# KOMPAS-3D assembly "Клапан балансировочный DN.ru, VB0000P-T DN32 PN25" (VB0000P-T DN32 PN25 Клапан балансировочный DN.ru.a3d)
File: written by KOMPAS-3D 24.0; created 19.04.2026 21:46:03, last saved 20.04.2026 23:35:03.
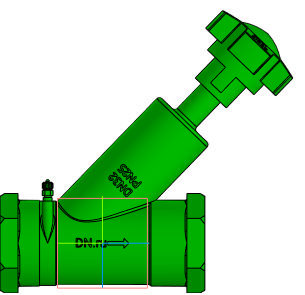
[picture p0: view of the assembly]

Document properties: Автор: DN.ru; Полное имя файла: C:\Работа\VB0000P-T DN X PN 25 Клапан балансировочный DN.ru\DN32\исходные материалы\VB0000P-T DN32 PN25 Клапан балансировочный DN.ru.a3d

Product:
- Component [detail]: Деталь  | qty 1  | pos. 1  | Масса: 0.00084; Раздел спецификации: Прочие изделия; Примечание: D080-01177; Автор: mrdid; source file: VB0000P-T DN32 PN25 Клапан балансировочный DN.ru.m3d
- Component [detail]: Деталь2  | qty 1  | pos. 2  | Масса: 0.358794; Автор: tyuri; additional columns: Типовые; source file: Деталь2 - Деталь2.m3d
- Part/product: Клапан балансировочный DN.ru  | designation VB0000P-T DN32 PN25
    Масса: 1
    Раздел спецификации: Прочие изделия
    Примечание: D080-01178

Referenced files in C:\Работа\VB0000P-T DN X PN 25 Клапан балансировочный DN.ru\DN32\исходные материалы\: Деталь2 - Деталь2.m3d, VB0000P-T DN32 PN25 Клапан балансировочный DN.ru.m3d
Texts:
  VB0000P-T DN32 PN25
  Деталь2 Деталь2
  Плоскость XY.Начало координат
  Плоскость ZY.Начало координат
